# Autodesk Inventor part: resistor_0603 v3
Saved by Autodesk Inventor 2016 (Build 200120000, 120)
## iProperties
Created: 2016-09
Part Number: resistor_0603 v3
Material: Generic
Document SubType Name: Modeling
Designer: Administrator
Appearance: Generic
Author: Administrator
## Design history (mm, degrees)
feature "Body6"
feature "Body8"
feature "Body19"
body "Solid1"
body "Solid2"
body "Solid3"
